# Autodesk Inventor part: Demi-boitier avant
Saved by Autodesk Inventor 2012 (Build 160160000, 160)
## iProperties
Created: 2013-08
Part Number: Demi-boitier avant
Material: Default
Document SubType Name: Modeling
Designer: hilarion
Density: 1 g/cm^3
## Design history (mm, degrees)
node "Demi-boitier avant1"
node "Demi-boitier avant"
node "Base1"
